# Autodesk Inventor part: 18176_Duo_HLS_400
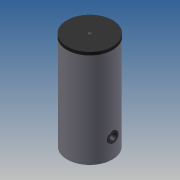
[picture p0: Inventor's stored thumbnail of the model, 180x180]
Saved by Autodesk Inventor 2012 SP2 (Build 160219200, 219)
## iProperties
allow_slope_adjustment: 0 ul
connection_type: 13 ul
flow_configuration2: 1 ul
flow_direction: 2 ul
loss_method: 0 ul
radius: 19,625 mm
radius: 15,375 mm
Created: 2014-05
Part Number: 18176_Duo_HLS_400
Material: Default
Document SubType Name: Modeling
Designer: michel
Density: 1 g/cm^3
radius: 12,250 mm
description: 0:0:18176_Duo_HLS_400
manufacturer: 0:0:Flamco Group
model: 0:0:Duo HLS 400
url: 0:0:www.flamcogroup.com
Author: michel
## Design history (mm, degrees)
sketch "Sketch1"
  geometry: C1 r 375 at (0, 0); 1 further point
  constraints: 1 centre point, 1 coincident
  dimensions: "d0" = 750 diameter of C1
extrude "Extrusion1" new body sketch "Sketch1" distance "d1" = 1630; taper "d2" = 0 deg
sketch "Sketch2"
  geometry: L1 (-375, 1630)-(375, 1630) reference; L2 (-375, 0)-(375, 0) reference; L3 (-375, 0)-(-375, 1630) reference; L4 (0, -342)-(0, 2052) reference; L5 (-504, 70)-(536, 70); L6 (-504, 330)-(536, 330); L7 (-490, 870)-(536, 870); L8 (-490, 970)-(536, 970); L9 (-490, 1470)-(536, 1470); L10 (375, 70)-(335, 70); L11 (335, 70)-(335, 86.625); L12 (335, 86.625)-(375, 86.625); L13 (375, 86.625)-(375, 70); L14 (335, 53.375)-(376, 53.375); L15 (376, 53.375)-(376, 54.625); L16 (376, 54.625)-(335, 54.625); L17 (335, 54.625)-(335, 53.375); L18 (375, 330)-(335, 330); L19 (335, 330)-(335, 350.955); L20 (335, 350.955)-(375, 350.955); L21 (375, 350.955)-(375, 330); L22 (335, 309.045)-(376, 309.045); L23 (376, 309.045)-(376, 310.375); L24 (376, 310.375)-(335, 310.375); L25 (335, 310.375)-(335, 309.045); L26 (375, 870)-(335, 870); L27 (335, 870)-(335, 883.22); L28 (335, 883.22)-(375, 883.22); L29 (375, 883.22)-(375, 870); L30 (335, 857.75)-(376, 857.75); L31 (376, 857.75)-(376, 856.78); L32 (376, 856.78)-(335, 856.78); L33 (335, 856.78)-(335, 857.75); L34 (375, 970)-(335, 970); L35 (335, 970)-(335, 990.955); L36 (335, 990.955)-(375, 990.955); L37 (375, 990.955)-(375, 970); L38 (335, 949.045)-(376, 949.045); L39 (376, 949.045)-(376, 950.375); L40 (376, 950.375)-(335, 950.375); L41 (335, 950.375)-(335, 949.045); L42 (375, 1470)-(335, 1470); L43 (335, 1470)-(335, 1486.625); L44 (335, 1486.625)-(375, 1486.625); L45 (375, 1486.625)-(375, 1470); L46 (335, 1453.375)-(376, 1453.375); L47 (376, 1453.375)-(376, 1454.625); L48 (376, 1454.625)-(335, 1454.625); L49 (335, 1454.625)-(335, 1453.375); L50 (0, 330)-(-504, 330); L51 (-375, 330)-(-387.5, 330); L52 (-387.5, 330)-(-387.5, 420); L53 (-387.5, 420)-(-375, 420); L54 (-375, 420)-(-375, 330); L55 (375, 1630)-(380, 1630); L56 (380, 1630)-(380, 1580); L57 (380, 1580)-(375, 1580); L58 (375, 1580)-(375, 1630); 2 further points
  constraints: 108 end point, 28 parallel, 13 perpendicular, 12 horizontal, 8 point on line, 6 other
  dimensions: "d6" = 70 distance from line of point (0, 0) L5; "d7" = 330 distance from line of point (0, 0) L6; "d8" = 870 distance from line of point (0, 0) L7; "d9" = 970 distance between parallel lines of L2 L8; "d10" = 1470 distance from line of point (0, 0) L9; "d15" = 16.625 distance of L10.end L11.end; "d16" = 16.625 distance between parallel lines of L5 L12 (derived); "d17" = 16.625 distance between parallel lines of L14 L5 (= d15); "d18" = 1.25 distance between parallel lines of L16 L14 (computed from d16); "d19" = 1 dimension on L15; "d22" = 40 distance from line of L12.end L11; "d23" = 41 distance from line of L14.end L17; "d24" = 20.955 distance of L18.end L19.end; "d25" = 40 distance from line of L20.end L19; "d26" = 20.955 distance between parallel lines of L6 L20 (derived); "d27" = 20.955 distance between parallel lines of L6 L22 (= d24); "d28" = 1.33 distance between parallel lines of L24 L22 (computed from d24); "d29" = 1 dimension on L23; "d30" = 41 distance between parallel lines of L23 L25; "d33" = 13.22 distance of L26.end L27.end; "d34" = 13.22 distance between parallel lines of L7 L28 (derived); "d35" = 40 dimension on L27; "d37" = 0.97 distance between parallel lines of L32 L30 (computed from d34); "d38" = 1 dimension on L31; "d39" = 41 distance between parallel lines of L31 L33; "d42" = 20.955 distance of L34.end L35.end; "d43" = 20.955 distance between parallel lines of L8 L36 (derived); "d44" = 40 distance from line of L36.end L35; "d45" = 20.955 distance between parallel lines of L38 L8 (= d42); "d46" = 1.33 distance between parallel lines of L40 L38 (computed from d42); "d47" = 1 dimension on L39; "d48" = 41 distance between parallel lines of L39 L41; "d49" = 16.625 distance of L42.end L43.end; "d50" = 40 distance from line of L44.end L43; "d51" = 16.625 distance between parallel lines of L9 L44 (derived); "d52" = 16.625 distance between parallel lines of L46 L9 (= d49); "d53" = 1.25 distance between parallel lines of L48 L46 (computed from d49); "d54" = 1 dimension on L47; "d55" = 41 distance between parallel lines of L47 L49; "d80" = 330 distance from line of point (0, 0) L50; "d81" = 12.5 distance of L52.end L53.end; "d82" = 90 distance of L51.end L52.end; "d83" = 90 distance between parallel lines of L50 L53 (derived); "d109" = 13.22 distance between parallel lines of L7 L32 (= d33); "d110" = 5 distance of L56.end L57.end; "d111" = 50 distance of L55.end L56.end
  node "Projected Loop1"
revolve "Revolution1" stored, may be unused: angle "d5" = 90 deg
revolve "Revolution2" stored, may be unused: angle "d20" = 90 deg
revolve "Revolution3" stored, may be unused: angle "d21" = 90 deg
revolve "Revolution4" stored, may be unused: angle "d31" = 90 deg
revolve "Revolution5" stored, may be unused: angle "d32" = 90 deg
revolve "Revolution6" stored, may be unused: angle "d40" = 90 deg
revolve "Revolution7" stored, may be unused: angle "d41" = 90 deg
revolve "Revolution8" stored, may be unused: angle "d72" = 90 deg
revolve "Revolution9" stored, may be unused: angle "d73" = 90 deg
revolve "Revolution10" stored, may be unused: angle "d74" = 90 deg
revolve "Revolution11" stored, may be unused: angle "d75" = 90 deg
revolve "Revolution16" stored, may be unused: angle "d84" = 90 deg
sketch "Sketch3"
  geometry: C1 r 62.5 at (0, 0); A1 r 90 centre (0, 0) between (90, 0) and (-90, 0) reference; 1 further point
  constraints: 1 centre point, 1 coincident
  dimensions: "d85" = 125 diameter of C1
extrude "Extrusion2" join sketch "Sketch3" stored distance "d86" = 1450; taper "d87" = 0 deg
sketch "Sketch4"
  geometry: C1 r 90 at (0, 0) reference; C2 r 55 at (0, 0); 1 further point
  constraints: 1 centre point, 1 coincident
  dimensions: "d88" = 110 diameter of C2
extrude "Extrusion3" cut sketch "Sketch4" distance "d89" = 80; taper "d90" = 0 deg
workplane "Work Plane1"
sketch "Sketch6"
  geometry: C1 r 335 at (0, 0) reference; C2 r 20.955 at (0, 0); C3 r 19.625 at (0, 0)
  constraints: 2 centre point, 2 coincident
  dimensions: "d103" = 41.91 diameter of C2; "d104" = 39.25 diameter of C3
extrude "Extrusion4" cut sketch "Sketch6" distance "d105" = 40; taper "d106" = 0 deg
extrude "Extrusion5" join sketch "Sketch6" distance "d107" = 2; taper "d108" = 0 deg
body "Solid1"
other parameters: "d91" = 45 deg
